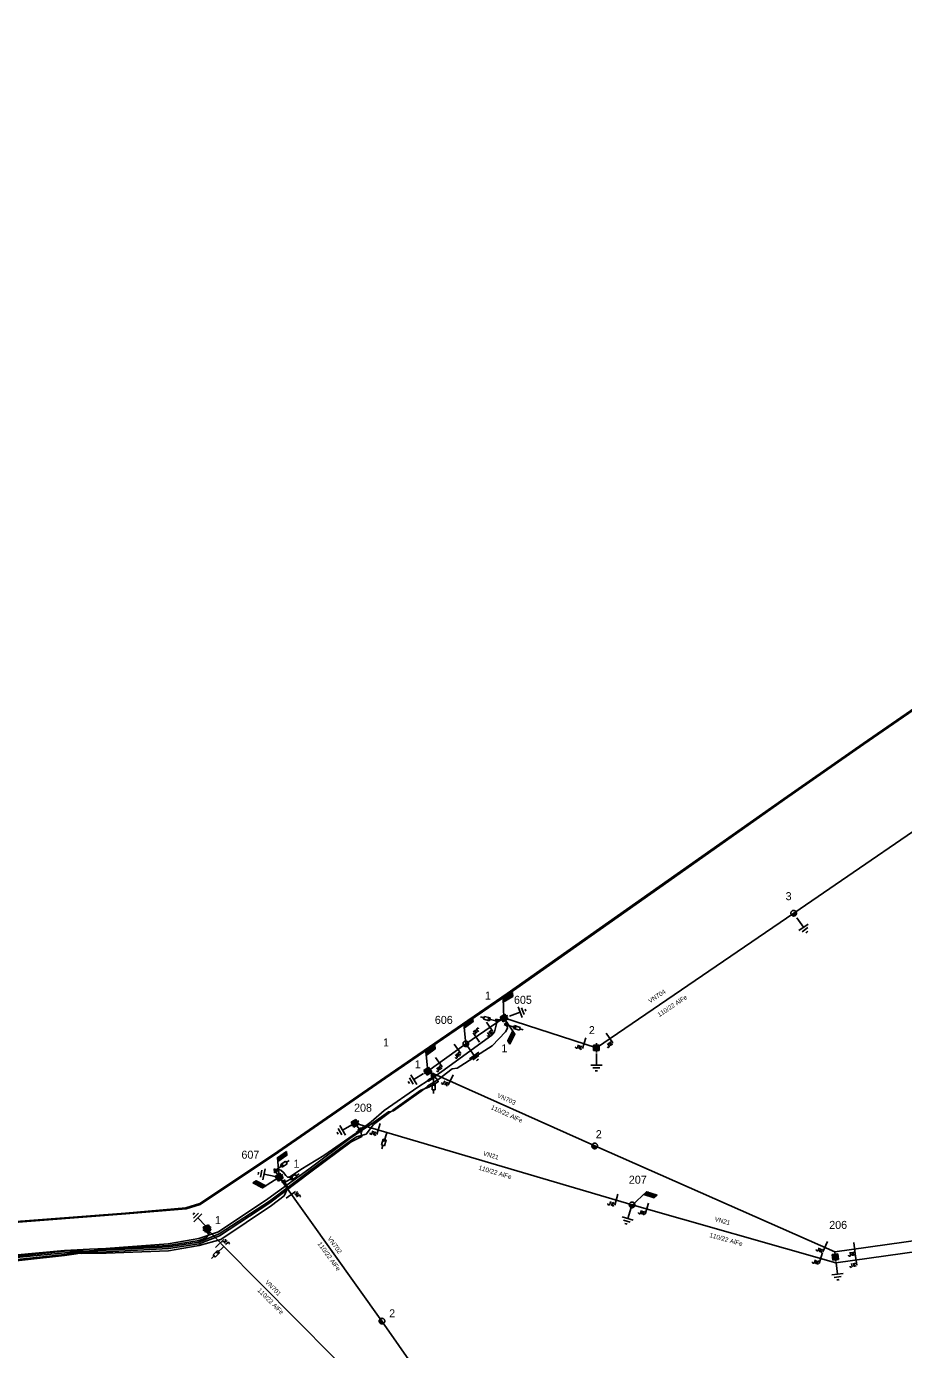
# Model space of a CAD drawing. Extents: x -545588 to -543214, y -1196037 to -1194452.
# Drawn here: x -545200.6 to -545008.8, y -1194920.5 to -1194631.3 of the extents above; entities that cross this region are included whole.
import ezdxf

# ---------------------------------------------------------------- set-up
doc = ezdxf.new("R2010")
doc.units = 0
for name, color, linetype in [('DOPLŇ_POPISY', 7, 'Continuous'), ('ELE_EON', 7, 'Continuous'), ('ELE_EON_POPIS', 7, 'Continuous'), ('Implicitní', 7, 'Continuous'), ('KONEC_VEDENÍ', 7, 'Continuous'), ('POL_ZNAČKA_PRACOVNÍ', 7, 'Continuous'), ('POL_ČÍSLO_PRACOVNÍ', 7, 'Continuous'), ('SDEL_EON', 7, 'Continuous'), ('SDEL_EON_POPIS', 7, 'Continuous'), ('TECH_OCHR_PÁSMO_HRAN', 7, 'Continuous'), ('Vrstva 18', 7, 'Continuous'), ('Vrstva 19', 7, 'Continuous'), ('Vrstva 20', 7, 'Continuous'), ('Vrstva 52', 7, 'Continuous'), ('ZP_EON', 7, 'Continuous')]:
    doc.layers.add(name, color=color, linetype=linetype)

# ---------------------------------------------------------------- blocks, each defined once
blk = doc.blocks.new('VN840')
at = {"layer": 'POL_ZNAČKA_PRACOVNÍ'}
for points in [[(-0.01, 1.41), (-0.01, -1.09)], [(-1.51, -1.24), (-1.51, -1.15)], [(-1.48, -1.35), (-1.51, -1.24)], [(-1.33, -1.42), (-1.48, -1.35)], [(-1.27, -1.42), (-1.33, -1.42)], [(-1.13, -1.35), (-1.27, -1.42)], [(-1.09, -1.24), (-1.13, -1.35)], [(-1.09, -0.59), (-1.09, -1.24)], [(-0.68, -0.59), (-0.68, -1.42)], [(-0.68, -1.11), (-0.27, -0.59)], [(-0.54, -0.94), (-0.2, -1.42)]]:
    blk.add_lwpolyline(points, dxfattribs=at)
blk = doc.blocks.new('VN440')
at = {"layer": 'ELE_EON_POPIS'}
for points in [[(1.22, 0), (1.21, 0.13), (1.19, 0.25), (1.16, 0.38), (1.11, 0.5), (1.05, 0.61), (0.98, 0.72), (0.9, 0.82), (0.81, 0.91), (0.71, 0.99), (0.6, 1.06), (0.49, 1.12), (0.37, 1.16), (0.25, 1.2), (0.12, 1.22), (-0.01, 1.22), (-0.14, 1.22), (-0.26, 1.2), (-0.39, 1.16), (-0.51, 1.12), (-0.62, 1.06), (-0.73, 0.99), (-0.83, 0.91), (-0.92, 0.82), (-1, 0.72), (-1.07, 0.61), (-1.13, 0.5), (-1.18, 0.38), (-1.21, 0.25), (-1.23, 0.13), (-1.24, 0), (-1.23, -0.13), (-1.21, -0.26), (-1.18, -0.38), (-1.13, -0.5), (-1.07, -0.62), (-1, -0.73), (-0.92, -0.83), (-0.83, -0.92), (-0.73, -1), (-0.62, -1.07), (-0.51, -1.13), (-0.39, -1.17), (-0.26, -1.2), (-0.14, -1.23), (-0.01, -1.23), (0.12, -1.23), (0.25, -1.2), (0.37, -1.17), (0.49, -1.13), (0.6, -1.07), (0.71, -1), (0.81, -0.92), (0.9, -0.83), (0.98, -0.73), (1.05, -0.62), (1.11, -0.5), (1.16, -0.38), (1.19, -0.26), (1.21, -0.13), (1.22, 0)], [(-1.24, 0), (1.22, 0)], [(-1.18, -0.34), (1.1, -0.34)], [(-1.01, -0.63), (0.97, -0.63)], [(-0.74, -0.92), (0.68, -0.92)]]:
    blk.add_lwpolyline(points, dxfattribs=at)
blk = doc.blocks.new('VN890')
at = {"layer": 'SDEL_EON_POPIS'}
for points in [[(-0.41, 0.41), (0.41, 0)], [(-0.41, -0.41), (-0.41, 0.41)], [(0.41, 0), (-0.41, -0.41)], [(-0.34, 0.31), (0.27, 0), (-0.34, -0.3), (-0.34, 0.31)], [(-0.26, 0.2), (0.1, 0), (-0.26, -0.18), (-0.26, 0.2)], [(-0.19, 0.09), (-0.04, 0), (-0.19, -0.08), (-0.19, 0.09)], [(-0.16, -0.01), (-0.16, 0.03), (-0.13, 0.01), (-0.16, -0.01)]]:
    blk.add_lwpolyline(points, dxfattribs=at)
blk = doc.blocks.new('VN820')
at = {"layer": 'DOPLŇ_POPISY'}
for points in [[(0, 0), (0, -2.1)], [(-0.32, -1.63), (0.34, -1.63)], [(-0.32, -2.95), (-0.32, -1.63)], [(0, -2.1), (-0.12, -1.86)], [(0, -2.1), (0.12, -1.86)], [(0.34, -1.63), (0.34, -2.95)], [(0.34, -2.95), (-0.32, -2.95)], [(0, -2.95), (0, -3.75)]]:
    blk.add_lwpolyline(points, dxfattribs=at)
blk = doc.blocks.new('VN810')
at = {"layer": 'POL_ZNAČKA_PRACOVNÍ'}
for points in [[(0, -1.25), (0, -3.75)], [(1.25, -3.75), (-1.25, -3.75)], [(0.77, -4.37), (-0.8, -4.37)], [(0, -5), (-0.25, -5)], [(0.27, -5), (0, -5)]]:
    blk.add_lwpolyline(points, dxfattribs=at)
blk = doc.blocks.new('VN001')
at = {"layer": 'Implicitní'}
for p, q in [((1.73, 3.03), (4.14, 3.03)), ((1.76, 3.08), (4.17, 3.08)), ((1.79, 3.13), (4.2, 3.13)), ((1.82, 3.18), (4.23, 3.18)), ((1.85, 3.23), (4.26, 3.23)), ((1.87, 3.28), (4.29, 3.28)), ((1.9, 3.33), (4.32, 3.33)), ((1.93, 3.38), (4.35, 3.38)), ((1.96, 3.43), (4.37, 3.43)), ((1.99, 3.48), (4.4, 3.48)), ((2.02, 3.53), (4.43, 3.53)), ((2.05, 3.58), (4.46, 3.58)), ((2.07, 3.63), (4.49, 3.63)), ((2.1, 3.68), (4.52, 3.68)), ((2.13, 3.73), (2.54, 3.73))]:
    blk.add_line(p, q, dxfattribs=at)
blk.add_lwpolyline([(2.13, 3.73), (0, 0)], dxfattribs=at)
blk.add_lwpolyline([(4.55, 3.73), (2.13, 3.73), (1.7, 2.98), (4.12, 2.99)], close=True, dxfattribs=at)
blk = doc.blocks.new('VN470')
at = {"layer": 'ELE_EON_POPIS'}
for points in [[(-1.23, 1.22), (1.23, 1.22)], [(-1.23, -1.23), (-1.23, 1.22)], [(-0.92, 0.9), (0.92, 0.9)], [(-0.92, -0.95), (-0.92, 0.9)], [(-0.61, 0.61), (0.61, 0.61)], [(-0.61, -0.62), (-0.61, 0.61)], [(-0.31, -0.27), (-0.31, 0.34)], [(-0.31, 0.34), (0.31, 0.34)], [(0, 1.22), (0, 1.97)], [(0.31, 0.34), (0.31, -0.27)], [(0.61, 0.61), (0.61, -0.62)], [(0.92, 0.9), (0.92, -0.95)], [(1.23, 1.22), (1.23, -1.23)], [(1.23, -1.23), (-1.23, -1.23)], [(0.92, -0.95), (-0.92, -0.95)], [(0.61, -0.62), (-0.61, -0.62)], [(0.31, -0.27), (-0.31, -0.27)], [(0, -1.23), (0, -1.98)]]:
    blk.add_lwpolyline(points, dxfattribs=at)

msp = doc.modelspace()

# ---------------------------------------------------------------- linework, layer by layer
at = {"layer": 'ELE_EON'}
for points in [[(-545096.16, -1194848.04), (-545075.95, -1194854.58), (-545032.81, -1194825.14), (-544993.69, -1194798.32), (-544903.01, -1194736.22), (-544804.37, -1194669.21), (-544702.68, -1194600.1), (-544611.95, -1194519.78), (-544514.29, -1194451.62)], [(-544083.88, -1194767.33), (-544137.68, -1194774.97), (-544275.32, -1194794.17), (-544399.3, -1194811.66), (-544539.71, -1194831.51), (-544666.5, -1194849.29), (-544797.03, -1194867.27), (-544922.4, -1194884.94), (-545023.84, -1194899.15), (-545076.33, -1194876.03), (-545112.81, -1194859.66)], [(-545068.16, -1194888.91), (-545023.6, -1194901.6), (-544922.06, -1194887.4), (-544796.64, -1194869.77), (-544666.32, -1194851.78), (-544539.47, -1194833.99), (-544398.96, -1194814.1), (-544275.11, -1194796.62), (-544137.43, -1194777.48), (-544081.81, -1194769.58)], [(-545128.74, -1194871.05), (-545121.79, -1194873.05), (-545068.16, -1194888.91)], [(-545145.32, -1194882.87), (-545144.58, -1194883.9), (-545122.84, -1194914.32), (-545087.92, -1194964.41)], [(-545125.62, -1194930.11), (-545157.44, -1194897.99), (-545161.09, -1194894.1)]]:
    msp.add_lwpolyline(points, dxfattribs=at)
at = {"layer": 'Vrstva 20'}
for points in [[(-545112.81, -1194861.62), (-545111.28, -1194860.66), (-545111.12, -1194860.92), (-545112.65, -1194861.88)], [(-545128.49, -1194873.07), (-545127.02, -1194871.95), (-545126.84, -1194872.19), (-545128.31, -1194873.31)]]:
    msp.add_lwpolyline(points, close=True, dxfattribs=at)
at = {"layer": 'Vrstva 52'}
for points in [[(-545096.16, -1194848.04), (-545104.5, -1194853.69)], [(-545104.5, -1194853.69), (-545112.81, -1194859.66)]]:
    msp.add_lwpolyline(points, dxfattribs=at)
at = {"layer": 'ZP_EON'}
for points in [[(-545233.41, -1194894.88), (-545178.88, -1194890.69), (-545165.68, -1194889.55), (-545162.68, -1194888.62), (-545146.55, -1194877.89), (-545122.2, -1194861.06), (-545095.47, -1194842.73), (-545060.25, -1194817.94), (-545034.96, -1194800.14), (-545017.61, -1194788.01), (-544994.8, -1194772.3), (-544991.56, -1194771.33), (-544987.81, -1194767.38), (-544970.95, -1194755.62), (-544959.46, -1194747.69), (-544955.77, -1194745.88), (-544943.24, -1194736.48), (-544921.65, -1194721.82), (-544915.98, -1194718.78), (-544907.91, -1194712.46), (-544897.39, -1194705.06), (-544885.31, -1194696.62), (-544879.55, -1194692.83), (-544879.87, -1194692.29)], [(-545233.4, -1194895.08), (-545178.86, -1194890.89), (-545165.64, -1194889.75), (-545162.6, -1194888.8), (-545146.43, -1194878.05), (-545122.08, -1194861.22), (-545095.35, -1194842.89), (-545060.13, -1194818.1), (-545034.84, -1194800.3), (-545017.49, -1194788.17), (-544994.72, -1194772.48)], [(-545095.79, -1194848.6), (-545095.53, -1194849.57), (-545095.36, -1194850.24), (-545095.83, -1194851.09), (-545098.73, -1194854.12), (-545106.42, -1194859.04), (-545107.48, -1194859.18), (-545110.61, -1194861.57), (-545112.8, -1194862.88), (-545113.45, -1194863.46), (-545114.26, -1194864.07), (-545120.29, -1194868.36), (-545120.89, -1194868.47), (-545121.42, -1194868.57), (-545124.71, -1194870.88), (-545129.84, -1194874.43), (-545138.8, -1194881.11), (-545147.81, -1194887.61), (-545158.6, -1194894.81), (-545162.87, -1194896.28), (-545169.61, -1194897.45), (-545183.17, -1194898.43), (-545186.8, -1194898.6), (-545192.24, -1194898.85), (-545208.93, -1194900.39)], [(-545096.16, -1194848.04), (-545097.68, -1194848.78), (-545098.24, -1194851.06), (-545098.81, -1194851.8), (-545109.76, -1194859.75), (-545111.2, -1194860.79), (-545112.73, -1194861.75), (-545115.02, -1194863.14), (-545122.33, -1194868.25), (-545125.21, -1194870.74), (-545126.93, -1194872.07), (-545128.4, -1194873.19), (-545135.55, -1194878.12), (-545137.2, -1194879.11), (-545140.55, -1194881.18), (-545143.03, -1194882.86), (-545143.47, -1194882.86), (-545143.86, -1194882.51), (-545144.35, -1194881.8), (-545144.93, -1194881.35), (-545145.48, -1194881.2), (-545146.16, -1194881.36), (-545145.32, -1194882.87)], [(-545112.81, -1194859.66), (-545111.56, -1194860.79), (-545110.61, -1194861.57), (-545110.58, -1194861.99), (-545112.59, -1194863.17), (-545113.74, -1194863.61), (-545114.34, -1194863.84), (-545120.48, -1194868.18), (-545120.68, -1194868.39), (-545121.19, -1194868.73), (-545124.66, -1194871.31), (-545126.29, -1194873.47), (-545128.43, -1194874.01), (-545129.75, -1194874.9), (-545138.56, -1194881.39), (-545147.45, -1194888.07), (-545158.4, -1194895.27), (-545162.84, -1194897.08), (-545169.49, -1194898.08), (-545183.12, -1194898.78), (-545186.75, -1194898.94), (-545192.21, -1194899.03), (-545208.9, -1194900.78)], [(-545128.74, -1194871.05), (-545128.35, -1194871.62), (-545127.51, -1194872.65), (-545127.21, -1194873.94), (-545129.58, -1194875.1), (-545138.37, -1194881.68), (-545147.33, -1194888.47), (-545158.32, -1194895.7), (-545162.82, -1194897.39), (-545169.52, -1194898.44), (-545183.07, -1194899.14), (-545189.95, -1194899.24), (-545192.17, -1194899.42), (-545208.95, -1194900.99)], [(-545144.76, -1194883.43), (-545144.15, -1194884.04), (-545143.79, -1194884.4), (-545143.4, -1194885.15), (-545144.22, -1194886.95), (-545146.97, -1194889.02), (-545158.05, -1194896.49), (-545162.81, -1194897.81), (-545169.54, -1194898.98), (-545183.1, -1194899.45), (-545188.58, -1194899.56), (-545190.38, -1194899.49), (-545192.21, -1194899.78), (-545208.91, -1194901.48)], [(-545161.09, -1194894.1), (-545160.85, -1194894.72), (-545160.77, -1194895.02), (-545160.69, -1194895.33), (-545161.24, -1194896.13), (-545162.82, -1194896.69), (-545169.61, -1194897.77), (-545183.13, -1194898.59), (-545185.37, -1194898.78), (-545189.67, -1194899.61), (-545192.22, -1194899.97), (-545208.89, -1194901.81)]]:
    msp.add_lwpolyline(points, dxfattribs=at)

# ---------------------------------------------------------------- block references
at = {"layer": 'DOPLŇ_POPISY'}
for name, p, xscale, yscale, rotation in [('VN440', (-545032.81, -1194825.14), 0.5000000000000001, 0.5, 34.61069446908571), ('VN470', (-545096.16, -1194848.04), 0.49999999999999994, 0.5000000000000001, -55.38930558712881), ('VN440', (-545104.5, -1194853.69), 0.5, 0.5, 36.02518610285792), ('VN470', (-545075.95, -1194854.58), 0.49999999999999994, 0.5000000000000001, 179.99069427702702), ('VN470', (-545112.81, -1194859.66), 0.4999999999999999, 0.49999999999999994, -55.75354065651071), ('VN470', (-545128.74, -1194871.05), 0.5, 0.5, 119.94166934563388), ('VN440', (-545076.32, -1194876.03), 0.5000000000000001, 0.5, -24.236872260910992), ('VN470', (-545145.32, -1194882.87), 0.5, 0.5, 125.59545280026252), ('VN440', (-545068.15, -1194888.91), 0.5, 0.5, -17.48817510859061), ('VN470', (-545161.09, -1194894.1), 0.4999999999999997, 0.4999999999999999, 113.33509500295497), ('VN470', (-545023.71, -1194900.32), 0.49999999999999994, 0.4999999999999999, 6.796644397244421), ('VN440', (-545122.83, -1194914.32), 0.49999999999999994, 0.5000000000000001, -54.40895272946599)]:
    msp.add_blockref(name, p, dxfattribs=dict(at, xscale=xscale, yscale=yscale, rotation=rotation))
at = {"layer": 'POL_ZNAČKA_PRACOVNÍ'}
for p, rotation in [((-545032.81, -1194825.14), 34.61069446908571), ((-545096.16, -1194848.04), 109.73254112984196), ((-545104.88, -1194853.19), 36.02581938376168), ((-545075.95, -1194854.58), -0.009305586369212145), ((-545112.71, -1194859.53), -58.06982772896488), ((-545128.19, -1194870.73), -60.05833066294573), ((-545144.95, -1194882.97), -101.57163605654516), ((-545067.97, -1194888.31), -17.488175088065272), ((-545160.46, -1194894.42), -135.44435002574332), ((-545023.71, -1194900.32), 6.796644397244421)]:
    msp.add_blockref('VN810', p, dxfattribs=dict(at, rotation=rotation))
at = {"layer": 'POL_ČÍSLO_PRACOVNÍ'}
for p, rotation in [((-545097.66, -1194848.74), -104.41971112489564), ((-545095.53, -1194849.57), 73.2599749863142), ((-545111.56, -1194860.79), 0.09709432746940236), ((-545121.79, -1194873.05), -16.502700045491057), ((-545146.16, -1194881.36), 125.125952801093), ((-545144.15, -1194884.04), 120.75388891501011), ((-545157.44, -1194897.99), -45.30478607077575)]:
    msp.add_blockref('VN820', p, dxfattribs=dict(at, rotation=rotation))
at = {"layer": 'TECH_OCHR_PÁSMO_HRAN'}
for p, rotation in [((-545096.16, -1194848.04), 32.096245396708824), ((-545104.5, -1194853.69), 36.02518610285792), ((-545096.16, -1194848.04), -116.71277724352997), ((-545112.81, -1194859.66), 35.81319731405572), ((-545145.32, -1194882.87), 34.68804711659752), ((-545145.32, -1194882.87), 152.8339916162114), ((-545068.12, -1194888.96), -17.48817510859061)]:
    msp.add_blockref('VN001', p, dxfattribs=dict(at, rotation=rotation))
at = {"layer": 'Vrstva 18'}
for p, rotation in [((-545099.19, -1194850.09), 34.116055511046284), ((-545102.3, -1194852.2), -145.88552772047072), ((-545078.67, -1194853.7), -17.916263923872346), ((-545072.99, -1194852.56), 34.31077225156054), ((-545106.22, -1194854.91), 35.425294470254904), ((-545110.31, -1194857.82), 35.425294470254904), ((-545107.88, -1194861.73), -24.455816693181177), ((-545123.65, -1194872.5), -16.51080007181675), ((-545142.62, -1194886.64), 125.59358056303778), ((-545071.63, -1194887.93), -16.350033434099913), ((-545064.96, -1194889.86), -15.847444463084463), ((-545158.2, -1194897.23), 134.69061664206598), ((-545026, -1194898.2), -23.7348555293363), ((-545019.49, -1194898.54), 7.976258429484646), ((-545026.91, -1194900.66), -15.847444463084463), ((-545019.15, -1194900.98), 7.96286939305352)]:
    msp.add_blockref('VN840', p, dxfattribs=dict(at, rotation=rotation))
at = {"layer": 'Vrstva 19'}
for p, rotation in [((-545097.68, -1194848.78), -104.41971109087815), ((-545095.53, -1194849.57), -54.63753888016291), ((-545111.56, -1194860.79), -56.548316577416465), ((-545127.51, -1194872.65), -53.087622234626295), ((-545146.16, -1194881.36), 121.38319165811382), ((-545144.15, -1194884.04), -54.79701672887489), ((-545160.77, -1194895.01), -80.36246111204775)]:
    msp.add_blockref('VN890', p, dxfattribs=dict(at, rotation=rotation))

# ---------------------------------------------------------------- texts
at = {"layer": 'ELE_EON_POPIS'}
for rotation, p in [(33.492, (-545062.19, -1194847.87)), (335.544, (-545099.12, -1194867.93)), (343.489, (-545101.8, -1194881.2)), (344.153, (-545051.31, -1194895.93)), (305.591, (-545136.96, -1194897.43)), (314.704, (-545150.14, -1194907.68))]:
    msp.add_text('110/22 AlFe', height=1, rotation=rotation, dxfattribs=at).set_placement(p)
at = {"layer": 'KONEC_VEDENÍ'}
for s, p in [('605', (-545093.97, -1194844.95)), ('1', (-545122.6, -1194854.28)), ('1', (-545096.71, -1194855.53)), ('607', (-545153.56, -1194878.81))]:
    msp.add_text(s, height=1.75, dxfattribs=at).set_placement(p)
at = {"layer": 'POL_ZNAČKA_PRACOVNÍ'}
for s, p in [('3', (-545034.58, -1194822.29)), ('1', (-545100.32, -1194844.03)), ('606', (-545111.27, -1194849.34)), ('2', (-545077.6, -1194851.58)), ('1', (-545115.67, -1194859.04)), ('208', (-545128.93, -1194868.54)), ('2', (-545076.09, -1194874.33)), ('1', (-545142.18, -1194880.79)), ('207', (-545068.86, -1194884.28)), ('1', (-545159.36, -1194893.12)), ('206', (-545025.05, -1194894.16)), ('2', (-545121.26, -1194913.5))]:
    msp.add_text(s, height=1.75, dxfattribs=at).set_placement(p)
at = {"layer": 'SDEL_EON'}
for s, rotation, p in [('VN704', 33.69, (-545064.2, -1194844.87)), ('VN703', 335.544, (-545097.72, -1194865.36)), ('VN21', 343.489, (-545100.79, -1194878.06)), ('VN21', 344.153, (-545050.19, -1194892.43)), ('VN702', 305.591, (-545134.8, -1194896.27)), ('VN701', 314.704, (-545148.46, -1194905.92))]:
    msp.add_text(s, height=1, rotation=rotation, dxfattribs=at).set_placement(p)

doc.saveas('drawing.dxf')
